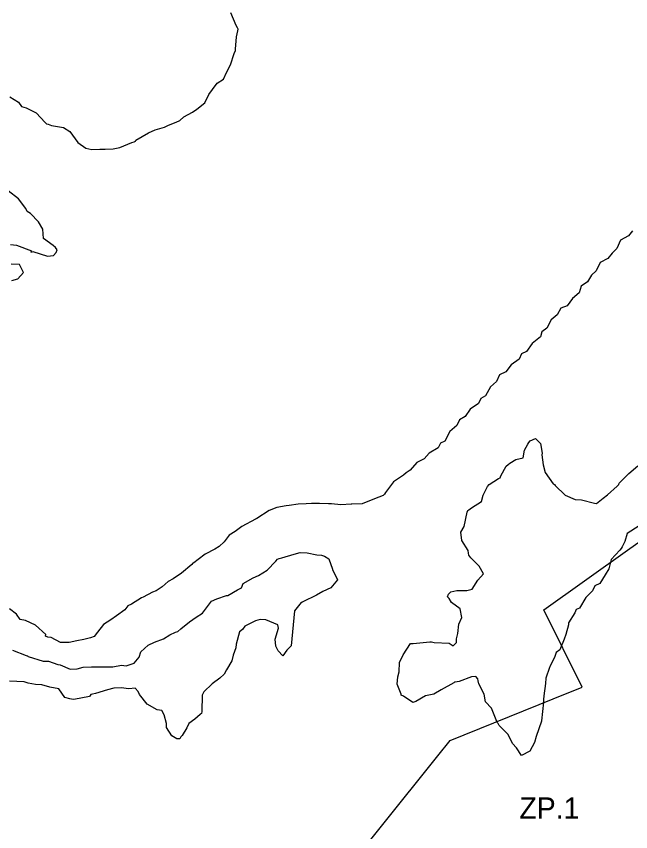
# Model space of a CAD drawing. Extents: x 7423571 to 7425893, y 5544590 to 5545833.
# Drawn here: x 7424447.1 to 7424591.2, y 5545056.2 to 5545247.5 of the extents above; entities that cross this region are included whole.
import ezdxf

# ---------------------------------------------------------------- set-up
doc = ezdxf.new("R2010")
doc.units = 0
for name, color, linetype in [('Default', 7, 'Continuous'), ('linie_rozgraniczające', 7, 'Continuous'), ('oznaczenia_przeznaczen', 7, 'Continuous')]:
    doc.layers.add(name, color=color, linetype=linetype)

msp = doc.modelspace()

# ---------------------------------------------------------------- linework, layer by layer
at = {"layer": 'Default'}
for points in [[(7424445.56, 5545228.59), (7424447.54, 5545227.38), (7424448.31, 5545226.36), (7424449.38, 5545226.07), (7424451.73, 5545224.85), (7424453.8, 5545222.63), (7424454.16, 5545222.27), (7424454.54, 5545222.19), (7424455.31, 5545221.92), (7424458.16, 5545221.39), (7424459.61, 5545220.51), (7424461.47, 5545217.93), (7424463.37, 5545216.61), (7424464.79, 5545216.26), (7424466.62, 5545216.31), (7424467.94, 5545216.35), (7424469.78, 5545216.4), (7424471.39, 5545216.72), (7424474.18, 5545217.91), (7424474.72, 5545218.05), (7424474.99, 5545218.21), (7424475.14, 5545218.49), (7424478.11, 5545220.14), (7424479.61, 5545220.87), (7424481.83, 5545221.52), (7424482.76, 5545222), (7424484.54, 5545222.7), (7424485.41, 5545223.03), (7424486.35, 5545223.95), (7424488.43, 5545225.05), (7424489.42, 5545225.73), (7424491.33, 5545227.19), (7424492.24, 5545229.19), (7424493.11, 5545230.35), (7424494.18, 5545231.85), (7424495.69, 5545232.78), (7424496.37, 5545234.36), (7424497.31, 5545236.1), (7424498.22, 5545238.76), (7424498.5, 5545239.45), (7424498.5, 5545239.81), (7424498.74, 5545242.67), (7424499.06, 5545244.1), (7424499.09, 5545244.48), (7424498.99, 5545244.81), (7424498.63, 5545245.33), (7424497.41, 5545248.31)], [(7424445.68, 5545193.95), (7424447.14, 5545193.79), (7424450.61, 5545192.47), (7424450.47, 5545192.18), (7424450.75, 5545192.26), (7424450.93, 5545192.31), (7424454.39, 5545191.23), (7424455.79, 5545191.41), (7424456.4, 5545192.07), (7424456.61, 5545192.72), (7424456.25, 5545193.25), (7424455.69, 5545193.78), (7424453.42, 5545195.38), (7424453.29, 5545197.59), (7424452.23, 5545199.32), (7424450.38, 5545201.23), (7424449.61, 5545201.69), (7424449.33, 5545202.43), (7424447.54, 5545204.66), (7424445.16, 5545206.58)], [(7424591.67, 5545197.18), (7424590.7, 5545196.02), (7424588.83, 5545194.99), (7424588, 5545193.05), (7424586.9, 5545191.96), (7424585.91, 5545190.7), (7424584.07, 5545189.77), (7424583.12, 5545187.84), (7424582.06, 5545186.81), (7424581.13, 5545185.24), (7424579.64, 5545184.24), (7424579.17, 5545182.68), (7424577.6, 5545181.31), (7424576.36, 5545179.57), (7424574.88, 5545179.01), (7424573.99, 5545177.47), (7424572.57, 5545176.33), (7424571.57, 5545174.38), (7424570.39, 5545173.52), (7424570.08, 5545172.3), (7424568.15, 5545170.78), (7424566.78, 5545168.88), (7424565.59, 5545168.33), (7424565.04, 5545167.1), (7424563.22, 5545165.72), (7424561.97, 5545164.15), (7424560.48, 5545163.43), (7424559.74, 5545161.88), (7424558.36, 5545160.57), (7424557.2, 5545158.51), (7424556.06, 5545157.88), (7424555.53, 5545156.7), (7424553.6, 5545155.35), (7424552.39, 5545153.66), (7424551.06, 5545152.88), (7424550.41, 5545151.49), (7424548.82, 5545150.13), (7424547.62, 5545147.86), (7424546.62, 5545147.36), (7424546.02, 5545146.31), (7424543.92, 5545145.03), (7424542.79, 5545143.67), (7424541.09, 5545142.83), (7424539.49, 5545141.04), (7424538.52, 5545140.39), (7424537.94, 5545139.87), (7424535.56, 5545138.32), (7424533.72, 5545135.8), (7424533.47, 5545135.44), (7424533.13, 5545135.13), (7424532.14, 5545134.74), (7424529.97, 5545133.85), (7424528.2, 5545133.18), (7424525.79, 5545133.06), (7424525.63, 5545133.05), (7424523.21, 5545132.93), (7424521.03, 5545133.12), (7424520.34, 5545133.12), (7424518.19, 5545133.26), (7424516.3, 5545133.2), (7424515.07, 5545133.17), (7424513.19, 5545133.11), (7424511.08, 5545132.75), (7424510.36, 5545132.7), (7424508.22, 5545132.27), (7424506.36, 5545131.58), (7424503.47, 5545129.72), (7424503.33, 5545129.64), (7424503.28, 5545129.61), (7424503.22, 5545129.56), (7424500, 5545127.83), (7424498.44, 5545126.66), (7424497.01, 5545125.77), (7424495.87, 5545124.26), (7424494.67, 5545123.12), (7424493.61, 5545122.53), (7424491.38, 5545121.35), (7424489.76, 5545120.06), (7424488.74, 5545119.3), (7424488.5, 5545119.2), (7424488.24, 5545118.94), (7424485.79, 5545116.89), (7424483.88, 5545115.56), (7424482.66, 5545114.96), (7424481.27, 5545113.66), (7424479.89, 5545112.71), (7424479.01, 5545112.41), (7424476.86, 5545111.29), (7424476.43, 5545111.08), (7424474.12, 5545109.64), (7424473.25, 5545109.21), (7424472.53, 5545108.3), (7424470.59, 5545106.86), (7424469.26, 5545105.94), (7424467.52, 5545104.88), (7424466.15, 5545103.04), (7424465.36, 5545102.06), (7424464.43, 5545101.7), (7424462.89, 5545101.35), (7424461.24, 5545101.05), (7424459.47, 5545100.61), (7424457.4, 5545100.61), (7424455.24, 5545101.78), (7424454.42, 5545101.86), (7424453.94, 5545102.08), (7424454.02, 5545102.54), (7424451.54, 5545104.69), (7424449.25, 5545105.8), (7424447.98, 5545106.04), (7424447.12, 5545107.27), (7424445.48, 5545108.54)], [(7424446.02, 5545185.51), (7424447.41, 5545185.93), (7424448.78, 5545187.4), (7424447.82, 5545189.31), (7424445.86, 5545189.37)], [(7424565.63, 5545074.13), (7424564.48, 5545075.93), (7424563.49, 5545076.96), (7424562.51, 5545079.01), (7424560.34, 5545081.17), (7424560.1, 5545081.61), (7424559.98, 5545081.82), (7424559.65, 5545082.45), (7424558.59, 5545085.19), (7424557.17, 5545086.71), (7424556.83, 5545088.49), (7424555.62, 5545090.97), (7424555.42, 5545091.65), (7424555.35, 5545092.11), (7424554.87, 5545092.68), (7424553.89, 5545092.57), (7424551, 5545091.47), (7424550.05, 5545091.3), (7424549.92, 5545091.32), (7424549.71, 5545091.2), (7424546.79, 5545089.5), (7424545.03, 5545088.5), (7424543.1, 5545088.08), (7424540.83, 5545086.79), (7424540.1, 5545086.52), (7424537.96, 5545088.01), (7424537.39, 5545088.27), (7424537.4, 5545088.54), (7424536.44, 5545090.88), (7424536.57, 5545092.6), (7424536.92, 5545093.78), (7424536.99, 5545095.9), (7424537.88, 5545097.71), (7424539.54, 5545100.37), (7424540.16, 5545100.41), (7424544.11, 5545100.77), (7424544.53, 5545100.8), (7424545.15, 5545100.62), (7424548.61, 5545100.44), (7424549.57, 5545099.84), (7424550.35, 5545100.64), (7424550.39, 5545101.45), (7424550.71, 5545102.72), (7424550.88, 5545104.96), (7424551.59, 5545106.5), (7424551.25, 5545108.52), (7424549.16, 5545109.97), (7424548.67, 5545110.94), (7424548.23, 5545111.37), (7424548.47, 5545111.99), (7424549.06, 5545112.54), (7424550.4, 5545112.81), (7424552.81, 5545112.79), (7424554.03, 5545113.17), (7424555.36, 5545115.25), (7424556.72, 5545116.72), (7424555.69, 5545118.55), (7424553.74, 5545120.45), (7424553.25, 5545121.13), (7424553.21, 5545121.58), (7424553.06, 5545122.18), (7424551.63, 5545124.58), (7424551.39, 5545126.51), (7424552.18, 5545127.81), (7424552.9, 5545131.17), (7424553.04, 5545131.58), (7424553.18, 5545131.69), (7424553.28, 5545131.75), (7424553.87, 5545132.22), (7424556.21, 5545133.7), (7424556.61, 5545135.19), (7424557.38, 5545136.76), (7424557.65, 5545137.19), (7424558.04, 5545137.67), (7424560.18, 5545139.07), (7424560.63, 5545139.24), (7424560.79, 5545139.73), (7424562.04, 5545141.95), (7424562.46, 5545142.37), (7424562.84, 5545142.68), (7424564.31, 5545143.54), (7424566, 5545143.91), (7424566.34, 5545145.75), (7424567.08, 5545147.16), (7424567.3, 5545147.52), (7424567.63, 5545147.95), (7424568.89, 5545148.51), (7424570.05, 5545147.28), (7424570.46, 5545145), (7424570.41, 5545144.66), (7424570.69, 5545142.31), (7424571.16, 5545140.54), (7424573.05, 5545137.86), (7424573.32, 5545137.68), (7424573.49, 5545137.42), (7424575.85, 5545135.21), (7424578.2, 5545134.14), (7424579.66, 5545134.11), (7424582.74, 5545133.29), (7424583.24, 5545133.26), (7424584.79, 5545134.47), (7424585.82, 5545135.25), (7424588.08, 5545137.27), (7424588.43, 5545137.66), (7424588.55, 5545138.03), (7424590.82, 5545140.27), (7424592.89, 5545142.1)], [(7424593.24, 5545127.99), (7424590.45, 5545126.18), (7424589.86, 5545124.32), (7424589.2, 5545123.04), (7424589, 5545122.71), (7424588.69, 5545122.32), (7424586.65, 5545120.07), (7424586.11, 5545117.91), (7424585.27, 5545116.53), (7424584, 5545114.47), (7424582.86, 5545113.94), (7424582.3, 5545112.75), (7424580.68, 5545111.15), (7424579.24, 5545108.69), (7424578.48, 5545108.37), (7424578.1, 5545107.58), (7424576.63, 5545105.26), (7424576.64, 5545104.76), (7424576.05, 5545102.49), (7424575.62, 5545101.39), (7424574.63, 5545098.89), (7424573.74, 5545098.31), (7424573.42, 5545097.38), (7424572.24, 5545094.88), (7424572.2, 5545094.74), (7424571.33, 5545092.29), (7424571.23, 5545091.01), (7424570.88, 5545088.09), (7424570.81, 5545087.27), (7424570.74, 5545086.65), (7424570.32, 5545082.27), (7424570.32, 5545082.24), (7424570.32, 5545082.23), (7424570.3, 5545082.17), (7424569.07, 5545078.57), (7424568.68, 5545077.17), (7424567.55, 5545075.16), (7424565.63, 5545074.13)], [(7424446.15, 5545098.84), (7424449.4, 5545097.54), (7424449.59, 5545097.47), (7424449.74, 5545097.52), (7424449.81, 5545097.37), (7424453.37, 5545096.24), (7424454.65, 5545096.23), (7424456.83, 5545095.5), (7424457.36, 5545095.35), (7424459.72, 5545094.39), (7424461.34, 5545094.45), (7424462.75, 5545094.85), (7424464.71, 5545094.92), (7424466.6, 5545094.95), (7424467.91, 5545094.9), (7424469.71, 5545094.92), (7424471.74, 5545095.3), (7424472.84, 5545095.16), (7424474.68, 5545095.79), (7424475.87, 5545097.17), (7424476.26, 5545098.44), (7424478, 5545100.02), (7424479.48, 5545100.72), (7424481.63, 5545101.49), (7424483.1, 5545102.41), (7424484.39, 5545103.07), (7424484.97, 5545103.22), (7424485.63, 5545103.83), (7424487.73, 5545105.48), (7424489.25, 5545106.54), (7424490.76, 5545107.5), (7424491.89, 5545109.08), (7424492.89, 5545110.33), (7424494.08, 5545110.86), (7424496.41, 5545111.63), (7424496.67, 5545111.66), (7424499, 5545112.98), (7424499.93, 5545113.46), (7424500.29, 5545114.43), (7424502.63, 5545115.78), (7424503.87, 5545116.32), (7424505.9, 5545117.58), (7424507.94, 5545119.74), (7424508.32, 5545120.16), (7424508.71, 5545120.3), (7424509.39, 5545120.49), (7424512.24, 5545121.35), (7424513.66, 5545121.74), (7424515.28, 5545121.66), (7424517.61, 5545121.21), (7424518.68, 5545121.13), (7424519.39, 5545120.9), (7424520.39, 5545120.25), (7424521.24, 5545117.86), (7424521.27, 5545117.73), (7424522.47, 5545115.33), (7424520.84, 5545113.42), (7424519.03, 5545112.59), (7424517.5, 5545111.69), (7424514.27, 5545110.13), (7424514.13, 5545110.06), (7424514.07, 5545110.04), (7424513.93, 5545109.98), (7424512.33, 5545108.04), (7424511.53, 5545099.87), (7424510.57, 5545098.85), (7424509.64, 5545097.46), (7424508.54, 5545098.7), (7424507.94, 5545099.73), (7424507.81, 5545101.4), (7424508.57, 5545103.95), (7424508.46, 5545104.75), (7424505.63, 5545105.98), (7424504.29, 5545106.02), (7424503.16, 5545105.68), (7424500.72, 5545104.44), (7424500.11, 5545103.68), (7424499.4, 5545103.11), (7424498.67, 5545100.2), (7424498.6, 5545099.35), (7424497.97, 5545097.67), (7424497.63, 5545096.35), (7424496.36, 5545094.25), (7424495.8, 5545093.23), (7424494.84, 5545092.26), (7424493.05, 5545090.96), (7424491.09, 5545089.04), (7424490.71, 5545088.3), (7424490.61, 5545084.48), (7424490.49, 5545084.01), (7424490.32, 5545083.85), (7424490.18, 5545083.7), (7424488.93, 5545082.65), (7424487.53, 5545081.62), (7424487.05, 5545080.61), (7424485.96, 5545078.82), (7424485.68, 5545078.52), (7424485.41, 5545078.02)], [(7424485.41, 5545078.02), (7424484.69, 5545078.05), (7424483.57, 5545078.72), (7424482.34, 5545080.72), (7424482.33, 5545081.6), (7424481.73, 5545083.65), (7424481.18, 5545084.67), (7424480.13, 5545084.87), (7424477.74, 5545086.16), (7424475.99, 5545088.42), (7424475.64, 5545089.1), (7424474.92, 5545089.88), (7424473.5, 5545089.75), (7424471.69, 5545090.03), (7424469.91, 5545089.91), (7424468.48, 5545089.56), (7424465.62, 5545088.66), (7424464.97, 5545088.49), (7424464.52, 5545088.41), (7424464.26, 5545087.95), (7424460.58, 5545087.23), (7424460.01, 5545087.32), (7424459.64, 5545087.39), (7424458.42, 5545087.71), (7424457.01, 5545089.76), (7424454.89, 5545090.14), (7424453.07, 5545090.69), (7424451.53, 5545090.77), (7424449.85, 5545091.1), (7424448.92, 5545091.42), (7424445.45, 5545091.56)]]:
    msp.add_lwpolyline(points, dxfattribs=at)
at = {"layer": 'linie_rozgraniczające'}
msp.add_lwpolyline([(7424510.23, 5545014.49), (7424505.42, 5545026.19), (7424509.67, 5545031.79), (7424519.51, 5545041.02), (7424545.99, 5545074.08), (7424548.87, 5545077.67), (7424573.07, 5545087.42), (7424579.84, 5545090.14), (7424570.85, 5545108.27), (7424590.52, 5545122.25), (7424613.92, 5545138.89)], dxfattribs=at)

# ---------------------------------------------------------------- texts
at = {"layer": 'oznaczenia_przeznaczen'}
msp.add_text('ZP.1', height=5, dxfattribs=at).set_placement((7424565.1, 5545059.29))

doc.saveas('drawing.dxf')
